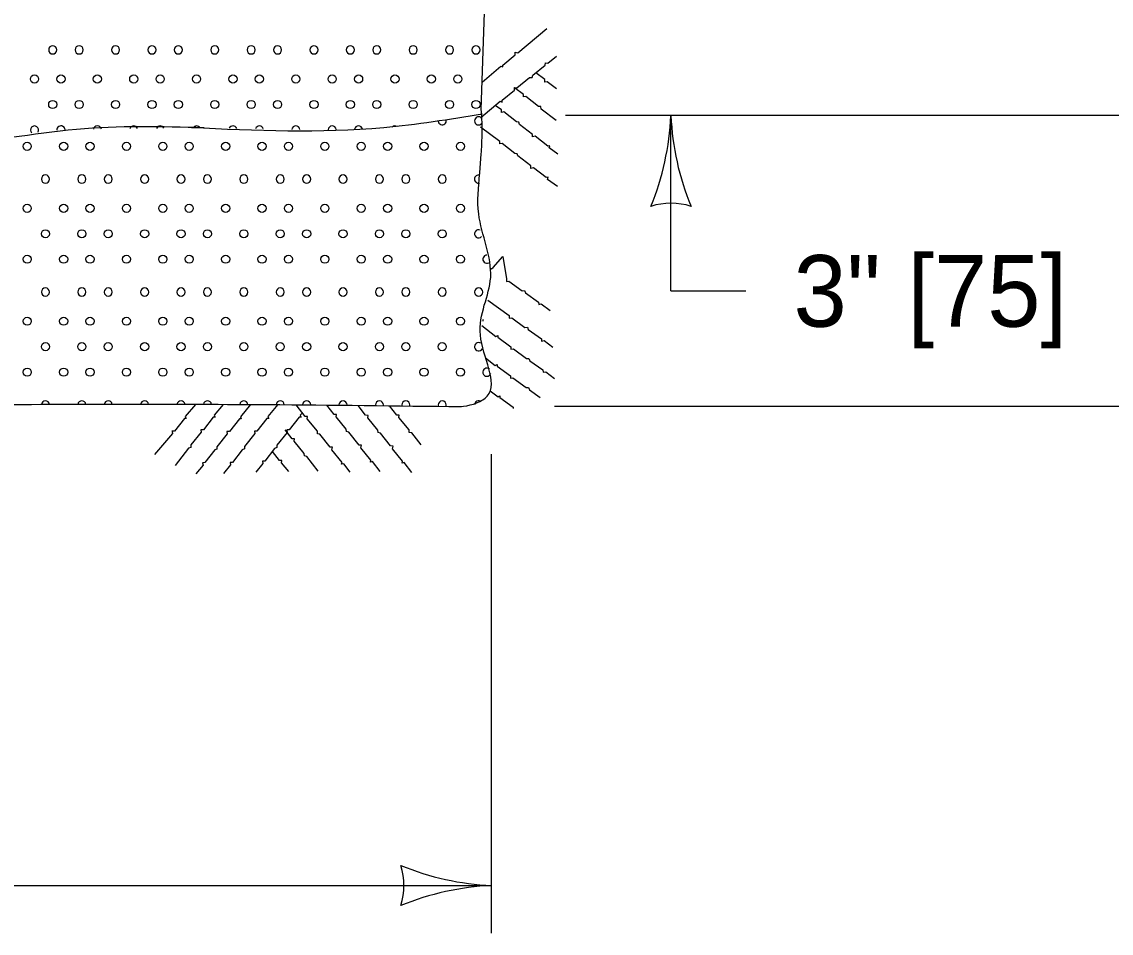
# Model space of a CAD drawing. Extents: x 49991.4 to 50021, y 49987.6 to 50011.4.
# Drawn here: x 50009.849 to 50010.762, y 49992.468 to 49993.231 of the extents above; entities that cross this region are included whole.
import ezdxf

# ---------------------------------------------------------------- set-up
doc = ezdxf.new("R2010")
doc.units = 0
for name, color, linetype in [('Level 1', 7, 'Continuous'), ('Level 2', 7, 'Continuous'), ('Level 3', 7, 'Continuous')]:
    doc.layers.add(name, color=color, linetype=linetype)

msp = doc.modelspace()

# ---------------------------------------------------------------- linework, layer by layer
at = {"layer": 'Level 1'}
for p, q in [((50009.9753, 49992.88776), (50009.9756, 49992.88646)), ((50009.9756, 49992.88646), (50009.9605, 49992.86876))]:
    msp.add_line(p, q, dxfattribs=at)
for points in [[(50010.23407, 49993.15763), (50010.23931, 49993.31242)], [(50010.23495, 49993.18062), (50010.25061, 49993.19412), (50010.25221, 49993.19332), (50010.25221, 49993.19492), (50010.26271, 49993.20342), (50010.26271, 49993.20562), (50010.26471, 49993.20532), (50010.28913, 49993.22559)], [(50010.23395, 49993.151), (50010.25001, 49993.16462), (50010.25161, 49993.16382), (50010.25161, 49993.16542), (50010.26211, 49993.17392), (50010.26201, 49993.17612), (50010.26411, 49993.17582), (50010.27471, 49993.18462), (50010.27671, 49993.18462), (50010.27731, 49993.18652), (50010.28781, 49993.19482), (50010.28791, 49993.19692), (50010.28991, 49993.19652), (50010.29711, 49993.20252)], [(50010.29711, 49993.17502), (50010.28951, 49993.18102), (50010.28751, 49993.18062), (50010.28751, 49993.18272), (50010.27991, 49993.18842)], [(50010.29691, 49993.14862), (50010.28451, 49993.15812), (50010.28411, 49993.16012), (50010.28211, 49993.16032), (50010.27161, 49993.16862), (50010.26961, 49993.16822), (50010.26951, 49993.17032), (50010.26211, 49993.17592)], [(50010.29831, 49993.12032), (50010.29111, 49993.12562), (50010.29151, 49993.12742), (50010.28991, 49993.12702), (50010.27931, 49993.13532), (50010.27721, 49993.13482), (50010.27701, 49993.13682), (50010.26611, 49993.14522), (50010.26561, 49993.14712), (50010.26361, 49993.14732), (50010.25311, 49993.15572), (50010.25111, 49993.15532), (50010.25101, 49993.15742), (50010.24596, 49993.16119)], [(50010.29801, 49993.09312), (50010.28971, 49993.09922), (50010.29011, 49993.10102), (50010.28861, 49993.10062), (50010.27791, 49993.10892), (50010.27581, 49993.10842), (50010.27561, 49993.11042), (50010.26471, 49993.11882), (50010.26421, 49993.12072), (50010.26221, 49993.12092), (50010.25171, 49993.12932), (50010.24971, 49993.12892), (50010.24971, 49993.13102), (50010.23368, 49993.14299)], [(50010.24127, 49993.02549), (50010.24267, 49993.02439), (50010.24427, 49993.02529), (50010.25227, 49993.03459), (50010.25527, 49993.01579), (50010.25537, 49993.01369), (50010.25737, 49993.01399), (50010.26847, 49993.00589), (50010.27047, 49993.00599), (50010.27127, 49993.00409), (50010.28217, 49992.99639), (50010.28237, 49992.99439), (50010.28437, 49992.99489), (50010.29187, 49992.98929)], [(50010.23959, 49992.99808), (50010.25767, 49992.98509), (50010.25767, 49992.98299), (50010.25977, 49992.98329), (50010.27077, 49992.97519), (50010.27287, 49992.97529), (50010.27357, 49992.97349), (50010.28457, 49992.96569), (50010.28477, 49992.96369), (50010.28677, 49992.96419), (50010.29417, 49992.95859)], [(50010.23461, 49992.97668), (50010.24637, 49992.96759), (50010.24797, 49992.96849), (50010.24807, 49992.96689), (50010.25897, 49992.95899), (50010.25907, 49992.95689), (50010.26107, 49992.95719), (50010.27217, 49992.94909), (50010.27417, 49992.94919), (50010.27497, 49992.94729), (50010.28587, 49992.93959), (50010.28607, 49992.93759), (50010.28817, 49992.93809), (50010.29557, 49992.93239)], [(50010.23767, 49992.94969), (50010.24597, 49992.94329), (50010.24747, 49992.94419), (50010.24757, 49992.94259), (50010.25857, 49992.93469), (50010.25867, 49992.93259), (50010.26057, 49992.93289), (50010.27177, 49992.92479), (50010.27377, 49992.92489), (50010.27447, 49992.92299), (50010.28357, 49992.91659)], [(50010.24163, 49992.92215), (50010.24827, 49992.91709), (50010.24977, 49992.91799), (50010.24987, 49992.91639), (50010.26087, 49992.90849), (50010.26087, 49992.90739)], [(50009.99472, 49992.91061), (50009.9863, 49992.90046), (50009.9871, 49992.89886), (50009.9855, 49992.89886), (50009.9771, 49992.88826), (50009.975, 49992.88826)], [(50010.01791, 49992.91062), (50010.0105, 49992.90166), (50010.0113, 49992.90006), (50010.0097, 49992.90006), (50010.0014, 49992.88946), (50009.9992, 49992.88946), (50009.9995, 49992.88746), (50009.9909, 49992.87676), (50009.9909, 49992.87466), (50009.989, 49992.87396), (50009.9778, 49992.85946)], [(50010.04102, 49992.91063), (50010.0324, 49992.90016), (50010.0332, 49992.89856), (50010.0316, 49992.89856), (50010.0233, 49992.88796), (50010.0211, 49992.88796), (50010.0214, 49992.88596), (50010.0128, 49992.87526), (50010.0128, 49992.87326), (50010.0109, 49992.87256), (50010.0027, 49992.86196), (50010.0007, 49992.86176), (50010.0011, 49992.85976), (50009.9952, 49992.85256)], [(50010.06384, 49992.91064), (50010.0554, 49992.90046), (50010.0563, 49992.89886), (50010.0547, 49992.89886), (50010.0463, 49992.88826), (50010.0442, 49992.88826), (50010.0444, 49992.88626), (50010.0358, 49992.87546), (50010.0358, 49992.87346), (50010.034, 49992.87276), (50010.0258, 49992.86216), (50010.0238, 49992.86206), (50010.0241, 49992.86006), (50010.0182, 49992.85286)], [(50010.1244, 49992.85386), (50010.119, 49992.86096), (50010.1172, 49992.86056), (50010.1176, 49992.86216), (50010.1091, 49992.87266), (50010.1096, 49992.87476), (50010.1076, 49992.87496), (50010.0991, 49992.88576), (50010.0971, 49992.88616), (50010.0969, 49992.88816), (50010.0884, 49992.89856), (50010.0887, 49992.90056), (50010.0867, 49992.90066), (50010.07921, 49992.91039)], [(50010.1495, 49992.85456), (50010.1432, 49992.86276), (50010.1415, 49992.86236), (50010.1418, 49992.86386), (50010.1334, 49992.87436), (50010.1339, 49992.87646), (50010.1318, 49992.87666), (50010.1233, 49992.88746), (50010.1213, 49992.88796), (50010.1211, 49992.88996), (50010.1126, 49992.90026), (50010.1129, 49992.90226), (50010.1109, 49992.90236), (50010.10476, 49992.91015)], [(50010.1759, 49992.85376), (50010.1696, 49992.86196), (50010.1679, 49992.86156), (50010.1682, 49992.86306), (50010.1598, 49992.87356), (50010.1603, 49992.87566), (50010.1582, 49992.87586), (50010.1497, 49992.88666), (50010.1478, 49992.88716), (50010.1475, 49992.88906), (50010.1391, 49992.89946), (50010.1394, 49992.90146), (50010.1373, 49992.90156), (50010.13096, 49992.90985)], [(50010.1838, 49992.87676), (50010.1759, 49992.88676), (50010.1739, 49992.88726), (50010.1737, 49992.88926), (50010.1652, 49992.89966), (50010.1655, 49992.90166), (50010.1634, 49992.90166), (50010.15746, 49992.90954)], [(50010.08435, 49992.90372), (50010.0825, 49992.90156), (50010.0834, 49992.89996), (50010.0817, 49992.89996), (50010.0734, 49992.88936), (50010.0713, 49992.88936), (50010.0715, 49992.88726), (50010.0629, 49992.87656), (50010.0629, 49992.87456), (50010.0611, 49992.87386), (50010.0529, 49992.86326), (50010.0509, 49992.86316), (50010.0512, 49992.86116), (50010.0453, 49992.85386)], [(50010.0977, 49992.85486), (50010.0881, 49992.86706), (50010.0861, 49992.86756), (50010.0859, 49992.86946), (50010.0774, 49992.87986), (50010.0777, 49992.88186), (50010.0757, 49992.88196), (50010.07, 49992.88926)], [(50010.0729, 49992.85436), (50010.0669, 49992.86176), (50010.0672, 49992.86376), (50010.0651, 49992.86376), (50010.0593, 49992.87136)]]:
    msp.add_lwpolyline(points, dxfattribs=at)
for centre in [(50009.85999, 49993.18323), (50009.88213, 49993.18323), (50009.91261, 49993.18323), (50009.94309, 49993.18323), (50009.96523, 49993.18323), (50009.99571, 49993.18323), (50010.02619, 49993.18323), (50010.04833, 49993.18323), (50010.07881, 49993.18323), (50010.10929, 49993.18323), (50010.13143, 49993.18323), (50010.16191, 49993.18323), (50010.19239, 49993.18323), (50010.21453, 49993.18323), (50009.87523, 49993.1619), (50009.89737, 49993.1619), (50009.92785, 49993.1619), (50009.92785, 49993.1619), (50009.95833, 49993.1619), (50009.98047, 49993.1619), (50010.01095, 49993.1619), (50010.01095, 49993.1619), (50010.04143, 49993.1619), (50010.06357, 49993.1619), (50010.09405, 49993.1619), (50010.09405, 49993.1619), (50010.12453, 49993.1619), (50010.14667, 49993.1619), (50010.17715, 49993.1619), (50010.17715, 49993.1619), (50010.20763, 49993.1619), (50010.22977, 49993.1619), (50009.85386, 49993.1269), (50009.88434, 49993.1269), (50009.90648, 49993.1269), (50009.93696, 49993.1269), (50009.96744, 49993.1269), (50009.98958, 49993.1269), (50010.02006, 49993.1269), (50010.05054, 49993.1269), (50010.07268, 49993.1269), (50010.10316, 49993.1269), (50010.13364, 49993.1269), (50010.15578, 49993.1269), (50010.18626, 49993.1269), (50010.21674, 49993.1269), (50009.85386, 49993.07497), (50009.88434, 49993.07497), (50009.90648, 49993.07497), (50009.93696, 49993.07497), (50009.96744, 49993.07497), (50009.98958, 49993.07497), (50010.02006, 49993.07497), (50010.05054, 49993.07497), (50010.07268, 49993.07497), (50010.10316, 49993.07497), (50010.13364, 49993.07497), (50010.15578, 49993.07497), (50010.18626, 49993.07497), (50010.21674, 49993.07497), (50009.8691, 49993.05363), (50009.8691, 49993.05363), (50009.89958, 49993.05363), (50009.92172, 49993.05363), (50009.9522, 49993.05363), (50009.9522, 49993.05363), (50009.98268, 49993.05363), (50010.00482, 49993.05363), (50010.0353, 49993.05363), (50010.0353, 49993.05363), (50010.06578, 49993.05363), (50010.08792, 49993.05363), (50010.1184, 49993.05363), (50010.1184, 49993.05363), (50010.14888, 49993.05363), (50010.17102, 49993.05363), (50010.2015, 49993.05363), (50010.2015, 49993.05363), (50009.85386, 49993.0323), (50009.88434, 49993.0323), (50009.90648, 49993.0323), (50009.93696, 49993.0323), (50009.96744, 49993.0323), (50009.98958, 49993.0323), (50010.02006, 49993.0323), (50010.05054, 49993.0323), (50010.07268, 49993.0323), (50010.10316, 49993.0323), (50010.13364, 49993.0323), (50010.15578, 49993.0323), (50010.18626, 49993.0323), (50010.21674, 49993.0323), (50009.85386, 49992.98037), (50009.88434, 49992.98037), (50009.90648, 49992.98037), (50009.93696, 49992.98037), (50009.96744, 49992.98037), (50009.98958, 49992.98037), (50010.02006, 49992.98037), (50010.05054, 49992.98037), (50010.07268, 49992.98037), (50010.10316, 49992.98037), (50010.13364, 49992.98037), (50010.15578, 49992.98037), (50010.18626, 49992.98037), (50010.21674, 49992.98037), (50009.8691, 49992.95903), (50009.8691, 49992.95903), (50009.89958, 49992.95903), (50009.92172, 49992.95903), (50009.9522, 49992.95903), (50009.9522, 49992.95903), (50009.98268, 49992.95903), (50010.00482, 49992.95903), (50010.0353, 49992.95903), (50010.0353, 49992.95903), (50010.06578, 49992.95903), (50010.08792, 49992.95903), (50010.1184, 49992.95903), (50010.1184, 49992.95903), (50010.14888, 49992.95903), (50010.17102, 49992.95903), (50010.2015, 49992.95903), (50010.2015, 49992.95903), (50009.85386, 49992.9377), (50009.88434, 49992.9377), (50009.90648, 49992.9377), (50009.93696, 49992.9377), (50009.96744, 49992.9377), (50009.98958, 49992.9377), (50010.02006, 49992.9377), (50010.05054, 49992.9377), (50010.07268, 49992.9377), (50010.10316, 49992.9377), (50010.13364, 49992.9377), (50010.15578, 49992.9377), (50010.18626, 49992.9377), (50010.21674, 49992.9377)]:
    msp.add_circle(centre, 0.00341, dxfattribs=at)
for centre, start, end in [((50009.87523, 49993.20773), 0, 180), ((50009.87523, 49993.20762), 180, 0), ((50009.89737, 49993.20773), 0, 180), ((50009.89737, 49993.20762), 180, 0), ((50009.92785, 49993.20773), 0, 180), ((50009.92785, 49993.20762), 180, 0), ((50009.92785, 49993.20762), 180, 0), ((50009.95833, 49993.20773), 0, 180), ((50009.95833, 49993.20762), 180, 0), ((50009.98047, 49993.20773), 0, 180), ((50009.98047, 49993.20762), 180, 0), ((50010.01095, 49993.20773), 0, 180), ((50010.01095, 49993.20762), 180, 0), ((50010.01095, 49993.20762), 180, 0), ((50010.04143, 49993.20773), 0, 180), ((50010.04143, 49993.20762), 180, 0), ((50010.06357, 49993.20773), 0, 180), ((50010.06357, 49993.20762), 180, 0), ((50010.09405, 49993.20773), 0, 180), ((50010.09405, 49993.20762), 180, 0), ((50010.09405, 49993.20762), 180, 0), ((50010.12453, 49993.20773), 0, 180), ((50010.12453, 49993.20762), 180, 0), ((50010.14667, 49993.20773), 0, 180), ((50010.14667, 49993.20762), 180, 0), ((50010.17715, 49993.20773), 0, 180), ((50010.17715, 49993.20762), 180, 0), ((50010.17715, 49993.20762), 180, 0), ((50010.20763, 49993.20773), 0, 180), ((50010.20763, 49993.20762), 180, 0), ((50010.22977, 49993.20773), 0, 180), ((50010.22977, 49993.20762), 180, 0), ((50010.23198, 49993.14823), 35.11463, 322.7645), ((50009.85999, 49993.14056), 330.07441, 222.95736), ((50009.88213, 49993.14056), 2.70234, 184.5406), ((50009.91261, 49993.14056), 12.03605, 169.46459), ((50009.94309, 49993.14056), 18.98014, 162.52051), ((50009.96523, 49993.14056), 24.19778, 157.30287), ((50009.99571, 49993.14056), 32.2171, 147.37566), ((50010.02619, 49993.14056), 23.81442, 153.96577), ((50010.04833, 49993.14056), 14.83991, 162.50276), ((50010.07881, 49993.14056), 5.17038, 173.1581), ((50010.10929, 49993.14056), 4.92598, 176.38102), ((50010.13143, 49993.14056), 14.86564, 169.63361), ((50010.16191, 49993.14056), 55.68233, 135.70526), ((50010.2015, 49993.14823), 183.16091, 15.04419), ((50010.2015, 49993.14823), 183.16091, 15.04419), ((50009.8691, 49993.09946), 0, 180), ((50009.8691, 49993.09935), 180, 0), ((50009.8691, 49993.09935), 180, 0), ((50009.89958, 49993.09946), 0, 180), ((50009.89958, 49993.09935), 180, 0), ((50009.92172, 49993.09946), 0, 180), ((50009.92172, 49993.09935), 180, 0), ((50009.9522, 49993.09946), 0, 180), ((50009.9522, 49993.09935), 180, 0), ((50009.9522, 49993.09935), 180, 0), ((50009.98268, 49993.09946), 0, 180), ((50009.98268, 49993.09935), 180, 0), ((50010.00482, 49993.09946), 0, 180), ((50010.00482, 49993.09935), 180, 0), ((50010.0353, 49993.09946), 0, 180), ((50010.0353, 49993.09935), 180, 0), ((50010.0353, 49993.09935), 180, 0), ((50010.06578, 49993.09946), 0, 180), ((50010.06578, 49993.09935), 180, 0), ((50010.08792, 49993.09946), 0, 180), ((50010.08792, 49993.09935), 180, 0), ((50010.1184, 49993.09946), 0, 180), ((50010.1184, 49993.09935), 180, 0), ((50010.1184, 49993.09935), 180, 0), ((50010.14888, 49993.09946), 0, 180), ((50010.14888, 49993.09935), 180, 0), ((50010.17102, 49993.09946), 0, 180), ((50010.17102, 49993.09935), 180, 0), ((50010.2015, 49993.09946), 0, 180), ((50010.2015, 49993.09935), 180, 0), ((50010.2015, 49993.09935), 180, 0), ((50010.23198, 49993.09946), 75.81004, 180), ((50010.23198, 49993.09935), 180, 281.33299), ((50010.23198, 49993.05363), 65.94648, 318.10079), ((50010.23888, 49993.0323), 89.20349, 297.31622), ((50009.8691, 49993.00486), 0, 180), ((50009.89958, 49993.00486), 0, 180), ((50009.92172, 49993.00486), 0, 180), ((50009.9522, 49993.00486), 0, 180), ((50009.98268, 49993.00486), 0, 180), ((50010.00482, 49993.00486), 0, 180), ((50010.0353, 49993.00486), 0, 180), ((50010.06578, 49993.00486), 0, 180), ((50010.08792, 49993.00486), 0, 180), ((50010.1184, 49993.00486), 0, 180), ((50010.14888, 49993.00486), 0, 180), ((50010.17102, 49993.00486), 0, 180), ((50010.2015, 49993.00486), 0, 180), ((50010.23198, 49993.00486), 0, 180), ((50009.8691, 49993.00475), 180, 0), ((50009.8691, 49993.00475), 180, 0), ((50009.89958, 49993.00475), 180, 0), ((50009.92172, 49993.00475), 180, 0), ((50009.9522, 49993.00475), 180, 0), ((50009.9522, 49993.00475), 180, 0), ((50009.98268, 49993.00475), 180, 0), ((50010.00482, 49993.00475), 180, 0), ((50010.0353, 49993.00475), 180, 0), ((50010.0353, 49993.00475), 180, 0), ((50010.06578, 49993.00475), 180, 0), ((50010.08792, 49993.00475), 180, 0), ((50010.1184, 49993.00475), 180, 0), ((50010.1184, 49993.00475), 180, 0), ((50010.14888, 49993.00475), 180, 0), ((50010.17102, 49993.00475), 180, 0), ((50010.2015, 49993.00475), 180, 0), ((50010.2015, 49993.00475), 180, 0), ((50010.23198, 49993.00475), 180, 0), ((50010.23888, 49992.98037), 154.04789, 180.05615), ((50010.23198, 49992.95903), 57.96359, 329.05297), ((50010.23888, 49992.9377), 47.14973, 343.58557), ((50009.8691, 49992.91026), 6.27834, 173.97947), ((50009.89958, 49992.91026), 7.42639, 172.82252), ((50009.92172, 49992.91026), 8.14062, 172.06586), ((50009.9522, 49992.91026), 8.78475, 171.31647), ((50009.98268, 49992.91026), 8.80237, 171.1362), ((50010.00482, 49992.91026), 8.2951, 171.45883), ((50010.0353, 49992.91026), 6.66679, 172.83579), ((50010.06578, 49992.91026), 3.56896, 175.59454), ((50010.08792, 49992.91026), 0.3215, 178.62192), ((50010.1184, 49992.91026), 0, 180), ((50010.1184, 49992.91015), 180, 181.96305), ((50010.1184, 49992.91015), 180, 181.96305), ((50010.1184, 49992.91015), 356.73689, 0), ((50010.1184, 49992.91015), 356.73689, 0), ((50010.14888, 49992.91026), 0, 180), ((50010.14888, 49992.91015), 180, 187.97296), ((50010.14888, 49992.91015), 350.6547, 360), ((50010.17102, 49992.91026), 0, 180), ((50010.17102, 49992.91015), 180, 192.51282), ((50010.17102, 49992.91015), 346.12721, 0), ((50010.2015, 49992.91026), 0, 180), ((50010.2015, 49992.91015), 180, 198.62396), ((50010.2015, 49992.91015), 180, 198.62396), ((50010.2015, 49992.91015), 340.17969, 0), ((50010.2015, 49992.91015), 340.17969, 0), ((50010.23198, 49992.91026), 49.25813, 179.17594)]:
    msp.add_arc(centre, 0.00341, start, end, dxfattribs=at)
for points in [[(50010.23517, 49993.1538), (50010.15247, 49993.1424), (50009.99137, 49993.1424)], [(50010.23406, 49993.11949), (50010.23477, 49993.15023), (50010.23407, 49993.15763)], [(50010.00197, 49993.1424), (50009.89507, 49993.141), (50009.78577, 49993.1316), (50009.71207, 49993.141), (50009.63127, 49993.1424)], [(50010.23283, 49993.10324), (50010.23287, 49993.1039), (50010.23412, 49993.11948)], [(50010.20712, 49992.90897), (50010.21927, 49992.90919), (50010.23917, 49992.91769), (50010.23347, 49992.96879), (50010.24207, 49993.01709), (50010.23203, 49993.07045), (50010.23283, 49993.10324)], [(50009.79491, 49992.91051), (50010.04507, 49992.91063), (50010.20712, 49992.90897)]]:
    msp.add_spline(points, degree=3, dxfattribs=at)
at = {"layer": 'Level 3'}
for p, q in [((50011.18148, 49993.15266), (50010.30467, 49993.15266)), ((50010.39311, 49993.00576), (50010.39311, 49993.15266)), ((50010.39311, 49993.00576), (50010.45574, 49993.00576)), ((50011.18148, 49992.90897), (50010.29557, 49992.90897)), ((50010.24289, 49992.46774), (50010.24289, 49992.86897)), ((50008.2551, 49992.50774), (50010.24289, 49992.50774))]:
    msp.add_line(p, q, dxfattribs=at)
for centre, radius, start, end in [((50010.1604, 49993.16415), 0.233, 337.92284, 357.17269), ((50010.61525, 49993.16182), 0.22232, 182.36048, 202.54399), ((50010.39311, 49993.02445), 0.05477, 72.13882, 107.86118), ((50010.25205, 49992.72987), 0.22232, 247.45601, 267.63952), ((50010.11468, 49992.50774), 0.05477, 342.13882, 17.86118), ((50010.25438, 49992.27503), 0.233, 92.82731, 112.07716)]:
    msp.add_arc(centre, radius, start, end, dxfattribs=at)

# ---------------------------------------------------------------- texts
at = {"layer": 'Level 2'}
msp.add_text('3" [75]', height=0.06, rotation=360, dxfattribs=at).set_placement((50010.49574, 49992.97576))

doc.saveas('drawing.dxf')
